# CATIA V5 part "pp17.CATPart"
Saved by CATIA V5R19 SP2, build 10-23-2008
Part number: pp17
Publications: "Line.1", "Line.2", "Line.3", "Plane.1", "Plane.2"
Bounding box of the stored display mesh (mm): x -10 to 0, y -436 to 0, z -50 to 50
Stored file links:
  C:\Users\Welcome\Documents\thinkm2\pp17.CATPart
  C:\Users\Welcome\Documents\thinkm2\Brasmeca.CATProduct
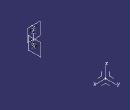
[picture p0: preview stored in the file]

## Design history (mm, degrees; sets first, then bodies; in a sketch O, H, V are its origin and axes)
AxisSystem1: origin (0, 0, 0), X (1, 0, 0), Y (0, 1, 0), Z (0, 0, 1)
Set1
  Point1: linked copy from another document
  Point2: linked copy from another document
Body1 (main body)
  Line1: type PtPt, FirstPoint Point1, SecondPoint Point2
  Line2: type PtDir, RefPoint Point1, Direction edge [XY plane of AxisSystem1 | ZX plane of AxisSystem1], Start 0, End -10
  Line3: type PtDir, RefPoint Point2, Direction edge [XY plane of AxisSystem1 | ZX plane of AxisSystem1], Start 0, End -10
  Plane1: type Normal, Curve Line3
  Point3: type OnCurve, Support Line1, Length 25
  Point4: type OnCurve, Support Line1, Length 75
  Line4: type PtDir, RefPoint Point3, Direction edge [YZ plane of AxisSystem1 | XY plane of AxisSystem1], Start 0, End -16
  Line5: type PtDir, RefPoint Point4, Direction edge [YZ plane of AxisSystem1 | XY plane of AxisSystem1], Start 0, End -15
  Plane2: type Normal, Curve Line4, RefPoint Point3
